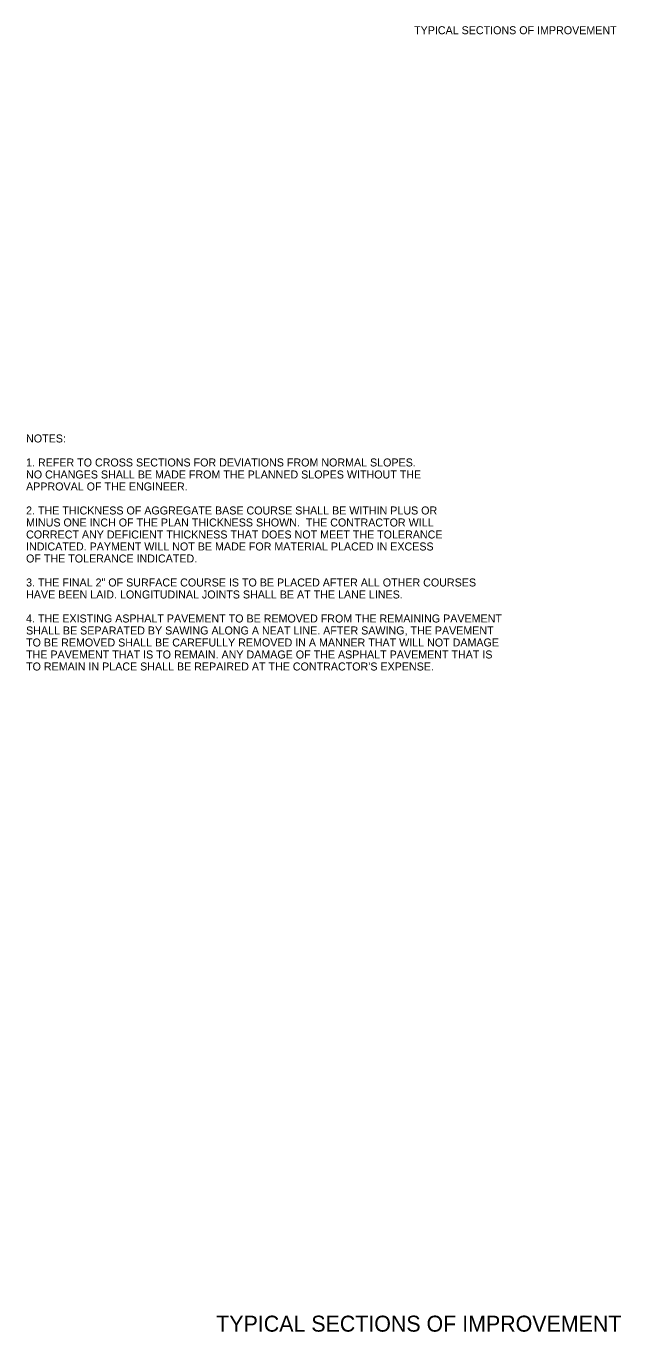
# Model space of a CAD drawing. Extents: x 138 to 3619, y -519 to 1449.
# Drawn here: x 3173 to 3619, y 38 to 1017 of the extents above; entities that cross this region are included whole.
import ezdxf

# ---------------------------------------------------------------- set-up
doc = ezdxf.new("R2010")
doc.units = 0
doc.layers.add('R_Annotation', color=7, linetype='Continuous')
doc.layers.add('R_Border', color=7, linetype='Continuous')

msp = doc.modelspace()

# ---------------------------------------------------------------- texts
at = {"layer": 'R_Annotation'}
for s, height, p in [('NOTES:', 6, (3172.81, 704.6)), ('1. REFER TO CROSS SECTIONS FOR DEVIATIONS FROM NORMAL SLOPES. ', 6, (3172.81, 686.6)), ('NO CHANGES SHALL BE MADE FROM THE PLANNED SLOPES WITHOUT THE', 6, (3172.81, 677.6)), ('APPROVAL OF THE ENGINEER.', 6, (3172.81, 668.6)), ('2. THE THICKNESS OF AGGREGATE BASE COURSE SHALL BE WITHIN PLUS OR', 6, (3172.81, 650.6)), ('MINUS ONE INCH OF THE PLAN THICKNESS SHOWN.  THE CONTRACTOR WILL', 6, (3172.81, 641.6)), ('CORRECT ANY DEFICIENT THICKNESS THAT DOES NOT MEET THE TOLERANCE', 6, (3172.81, 632.6)), ('INDICATED. PAYMENT WILL NOT BE MADE FOR MATERIAL PLACED IN EXCESS', 6, (3172.81, 623.6)), ('OF THE TOLERANCE INDICATED.', 6, (3172.81, 614.6)), ('3. THE FINAL 2" OF SURFACE COURSE IS TO BE PLACED AFTER ALL OTHER COURSES', 6, (3172.81, 596.6)), ('HAVE BEEN LAID. LONGITUDINAL JOINTS SHALL BE AT THE LANE LINES.', 6, (3172.81, 587.6)), ('4. THE EXISTING ASPHALT PAVEMENT TO BE REMOVED FROM THE REMAINING PAVEMENT', 6, (3172.81, 569.6)), ('SHALL BE SEPARATED BY SAWING ALONG A NEAT LINE. AFTER SAWING, THE PAVEMENT', 6, (3172.81, 560.6)), ('TO BE REMOVED SHALL BE CAREFULLY REMOVED IN A MANNER THAT WILL NOT DAMAGE', 6, (3172.81, 551.6)), ('THE PAVEMENT THAT IS TO REMAIN. ANY DAMAGE OF THE ASPHALT PAVEMENT THAT IS', 6, (3172.81, 542.6)), ("TO REMAIN IN PLACE SHALL BE REPAIRED AT THE CONTRACTOR'S EXPENSE.", 6, (3172.81, 533.6)), ('TYPICAL SECTIONS OF IMPROVEMENT', 12, (3315.51, 37.77))]:
    msp.add_text(s, height=height, dxfattribs=at).set_placement(p)
at = {"layer": 'R_Border'}
msp.add_text('TYPICAL SECTIONS OF IMPROVEMENT', height=6, dxfattribs=at).set_placement((3463.98, 1010.75))

doc.saveas('drawing.dxf')
